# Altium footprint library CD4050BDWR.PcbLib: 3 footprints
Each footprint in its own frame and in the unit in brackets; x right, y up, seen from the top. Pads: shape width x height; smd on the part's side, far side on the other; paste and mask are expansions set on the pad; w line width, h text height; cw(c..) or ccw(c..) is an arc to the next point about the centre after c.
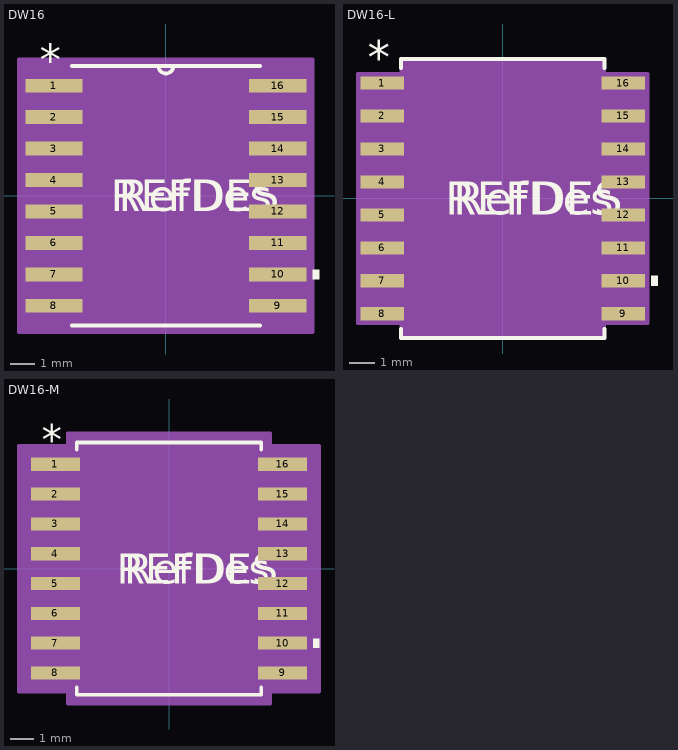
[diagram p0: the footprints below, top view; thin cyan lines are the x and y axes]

## DW16 [mil]
pads (16):
  rect 91x22 smd paste-45.5 mask-45.5: 1(-178,175) 2(-178,125) 3(-178,75) 4(-178,25) 5(-178,-25) 6(-178,-75) 7(-178,-125) 8(-178,-175) 9(178,-175) 10(178,-125) 11(178,-75) 12(178,-25) 13(178,25) 14(178,75) 15(178,125) 16(178,175)
Top Overlay:
  region: 233.5,-117.5 243.5,-117.5 243.5,-132.5 233.5,-132.5
  lines w6: -149.5,-206.5 149.5,-206.5 ; -149.5,206.5 149.5,206.5 ; -12,206.5 ccw(c0,206.5) 12,206.5
  text "REFDES" at -87.5,-25 h50
  text "*" at -200.5,192 h50
  text "RefDes" at -75,-25 h50
Mechanical 13:
  lines w0: -12,206.5 ccw(c0,206.5) 12,206.5
  lines w1: -209.5,-185 -209.5,-165 -149.5,-165 -149.5,-185 -209.5,-185 ; -209.5,-135 -209.5,-115 -149.5,-115 -149.5,-135 -209.5,-135 ; -209.5,-85 -209.5,-65 -149.5,-65 -149.5,-85 -209.5,-85 ; -209.5,-35 -209.5,-15 -149.5,-15 -149.5,-35 -209.5,-35 ; -209.5,15 -209.5,35 -149.5,35 -149.5,15 -209.5,15 ; -209.5,65 -209.5,85 -149.5,85 -149.5,65 -209.5,65 ; -209.5,115 -209.5,135 -149.5,135 -149.5,115 -209.5,115 ; -209.5,165 -209.5,185 -149.5,185 -149.5,165 -209.5,165 ; -149.5,-206.5 149.5,-206.5 149.5,206.5 -149.5,206.5 -149.5,-206.5 ; 149.5,-185 149.5,-165 209.5,-165 209.5,-185 149.5,-185 ; 149.5,-135 149.5,-115 209.5,-115 209.5,-135 149.5,-135 ; 149.5,-85 149.5,-65 209.5,-65 209.5,-85 149.5,-85 ; 149.5,-35 149.5,-15 209.5,-15 209.5,-35 149.5,-35 ; 149.5,15 149.5,35 209.5,35 209.5,15 149.5,15 ; 149.5,65 149.5,85 209.5,85 209.5,65 149.5,65 ; 149.5,115 149.5,135 209.5,135 209.5,115 149.5,115 ; 149.5,165 149.5,185 209.5,185 209.5,165 149.5,165
  text "*" at -200.5,192 h50
  text "RefDes2" at -87.5,-25 h50
Mechanical 15:
  region: 233.5,-216.5 -233.5,-216.5 -233.5,216.5 233.5,216.5
  lines w6: -233.5,-216.5 -233.5,216.5 233.5,216.5 233.5,-216.5 -233.5,-216.5
3D body "DW16.step": height 104.09, standoff 0, extent -209.49,-206.5 209.49,206.5

## DW16-L [mil]
pads (16):
  rect 66x20 smd paste+0 mask+0: 1(-182.5,175) 2(-182.5,125) 3(-182.5,75) 4(-182.5,25) 5(-182.5,-25) 6(-182.5,-75) 7(-182.5,-125) 8(-182.5,-175) 9(182.5,-175) 10(182.5,-125) 11(182.5,-75) 12(182.5,-25) 13(182.5,25) 14(182.5,75) 15(182.5,125) 16(182.5,175)
Top Overlay:
  region: 225.5,-117.5 235.5,-117.5 235.5,-132.5 225.5,-132.5
  lines w6: -154.5,-198.1 -154.5,-211.5 154.5,-211.5 154.5,-198.1 ; -154.5,198.1 -154.5,211.5 154.5,211.5 154.5,198.1
  text "REFDES" at -87.5,-25 h50
  text "*" at -205,190 h50
  text "RefDes" at -75,-25 h50
Mechanical 13:
  lines w0: -12,206.5 ccw(c0,206.5) 12,206.5
  lines w1: -209.5,-185 -209.5,-165 -149.5,-165 -149.5,-185 -209.5,-185 ; -209.5,-135 -209.5,-115 -149.5,-115 -149.5,-135 -209.5,-135 ; -209.5,-85 -209.5,-65 -149.5,-65 -149.5,-85 -209.5,-85 ; -209.5,-35 -209.5,-15 -149.5,-15 -149.5,-35 -209.5,-35 ; -209.5,15 -209.5,35 -149.5,35 -149.5,15 -209.5,15 ; -209.5,65 -209.5,85 -149.5,85 -149.5,65 -209.5,65 ; -209.5,115 -209.5,135 -149.5,135 -149.5,115 -209.5,115 ; -209.5,165 -209.5,185 -149.5,185 -149.5,165 -209.5,165 ; -149.5,-206.5 149.5,-206.5 149.5,206.5 -149.5,206.5 -149.5,-206.5 ; 149.5,-185 149.5,-165 209.5,-165 209.5,-185 149.5,-185 ; 149.5,-135 149.5,-115 209.5,-115 209.5,-135 149.5,-135 ; 149.5,-85 149.5,-65 209.5,-65 209.5,-85 149.5,-85 ; 149.5,-35 149.5,-15 209.5,-15 209.5,-35 149.5,-35 ; 149.5,15 149.5,35 209.5,35 209.5,15 149.5,15 ; 149.5,65 149.5,85 209.5,85 209.5,65 149.5,65 ; 149.5,115 149.5,135 209.5,135 209.5,115 149.5,115 ; 149.5,165 149.5,185 209.5,185 209.5,165 149.5,165
  text "*" at -147,153.5 h50
  text "RefDes2" at -87.5,-25 h50
Mechanical 15:
  region: -153.5,-189 -219.5,-189 -219.5,189 -153.5,189 -153.5,210.5 153.5,210.5 153.5,189 219.5,189 219.5,-189 153.5,-189 153.5,-210.5 -153.5,-210.5
  lines w6: -219.5,-189 -219.5,189 -153.5,189 -153.5,210.5 153.5,210.5 153.5,189 219.5,189 219.5,-189 153.5,-189 153.5,-210.5 -153.5,-210.5 -153.5,-189 -219.5,-189
3D body "DW16.step": height 104.09, standoff 0, extent -209.49,-206.5 209.49,206.5

## DW16-M [mil]
pads (16):
  rect 82x22 smd paste+0 mask+0: 1(-190.5,175) 2(-190.5,125) 3(-190.5,75) 4(-190.5,25) 5(-190.5,-25) 6(-190.5,-75) 7(-190.5,-125) 8(-190.5,-175) 9(190.5,-175) 10(190.5,-125) 11(190.5,-75) 12(190.5,-25) 13(190.5,25) 14(190.5,75) 15(190.5,125) 16(190.5,175)
Top Overlay:
  region: 241.5,-117.5 251.5,-117.5 251.5,-132.5 241.5,-132.5
  lines w6: -154.5,-199.1 -154.5,-211.5 154.5,-211.5 154.5,-199.1 ; -154.5,199.1 -154.5,211.5 154.5,211.5 154.5,199.1
  text "REFDES" at -87.5,-25 h50
  text "*" at -213,192 h50
  text "RefDes" at -75,-25 h50
Mechanical 13:
  lines w0: -12,206.5 ccw(c0,206.5) 12,206.5
  lines w1: -209.5,-185 -209.5,-165 -149.5,-165 -149.5,-185 -209.5,-185 ; -209.5,-135 -209.5,-115 -149.5,-115 -149.5,-135 -209.5,-135 ; -209.5,-85 -209.5,-65 -149.5,-65 -149.5,-85 -209.5,-85 ; -209.5,-35 -209.5,-15 -149.5,-15 -149.5,-35 -209.5,-35 ; -209.5,15 -209.5,35 -149.5,35 -149.5,15 -209.5,15 ; -209.5,65 -209.5,85 -149.5,85 -149.5,65 -209.5,65 ; -209.5,115 -209.5,135 -149.5,135 -149.5,115 -209.5,115 ; -209.5,165 -209.5,185 -149.5,185 -149.5,165 -209.5,165 ; -149.5,-206.5 149.5,-206.5 149.5,206.5 -149.5,206.5 -149.5,-206.5 ; 149.5,-185 149.5,-165 209.5,-165 209.5,-185 149.5,-185 ; 149.5,-135 149.5,-115 209.5,-115 209.5,-135 149.5,-135 ; 149.5,-85 149.5,-65 209.5,-65 209.5,-85 149.5,-85 ; 149.5,-35 149.5,-15 209.5,-15 209.5,-35 149.5,-35 ; 149.5,15 149.5,35 209.5,35 209.5,15 149.5,15 ; 149.5,65 149.5,85 209.5,85 209.5,65 149.5,65 ; 149.5,115 149.5,135 209.5,135 209.5,115 149.5,115 ; 149.5,165 149.5,185 209.5,185 209.5,165 149.5,165
  text "*" at -147,153.5 h50
  text "RefDes2" at -87.5,-25 h50
Mechanical 15:
  region: -169.5,-206 -251.5,-206 -251.5,206 -169.5,206 -169.5,226.5 169.5,226.5 169.5,206 251.5,206 251.5,-206 169.5,-206 169.5,-226.5 -169.5,-226.5
  lines w6: -251.5,-206 -251.5,206 -169.5,206 -169.5,226.5 169.5,226.5 169.5,206 251.5,206 251.5,-206 169.5,-206 169.5,-226.5 -169.5,-226.5 -169.5,-206 -251.5,-206
3D body "DW16.step": height 104.09, standoff 0, extent -209.49,-206.5 209.49,206.5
